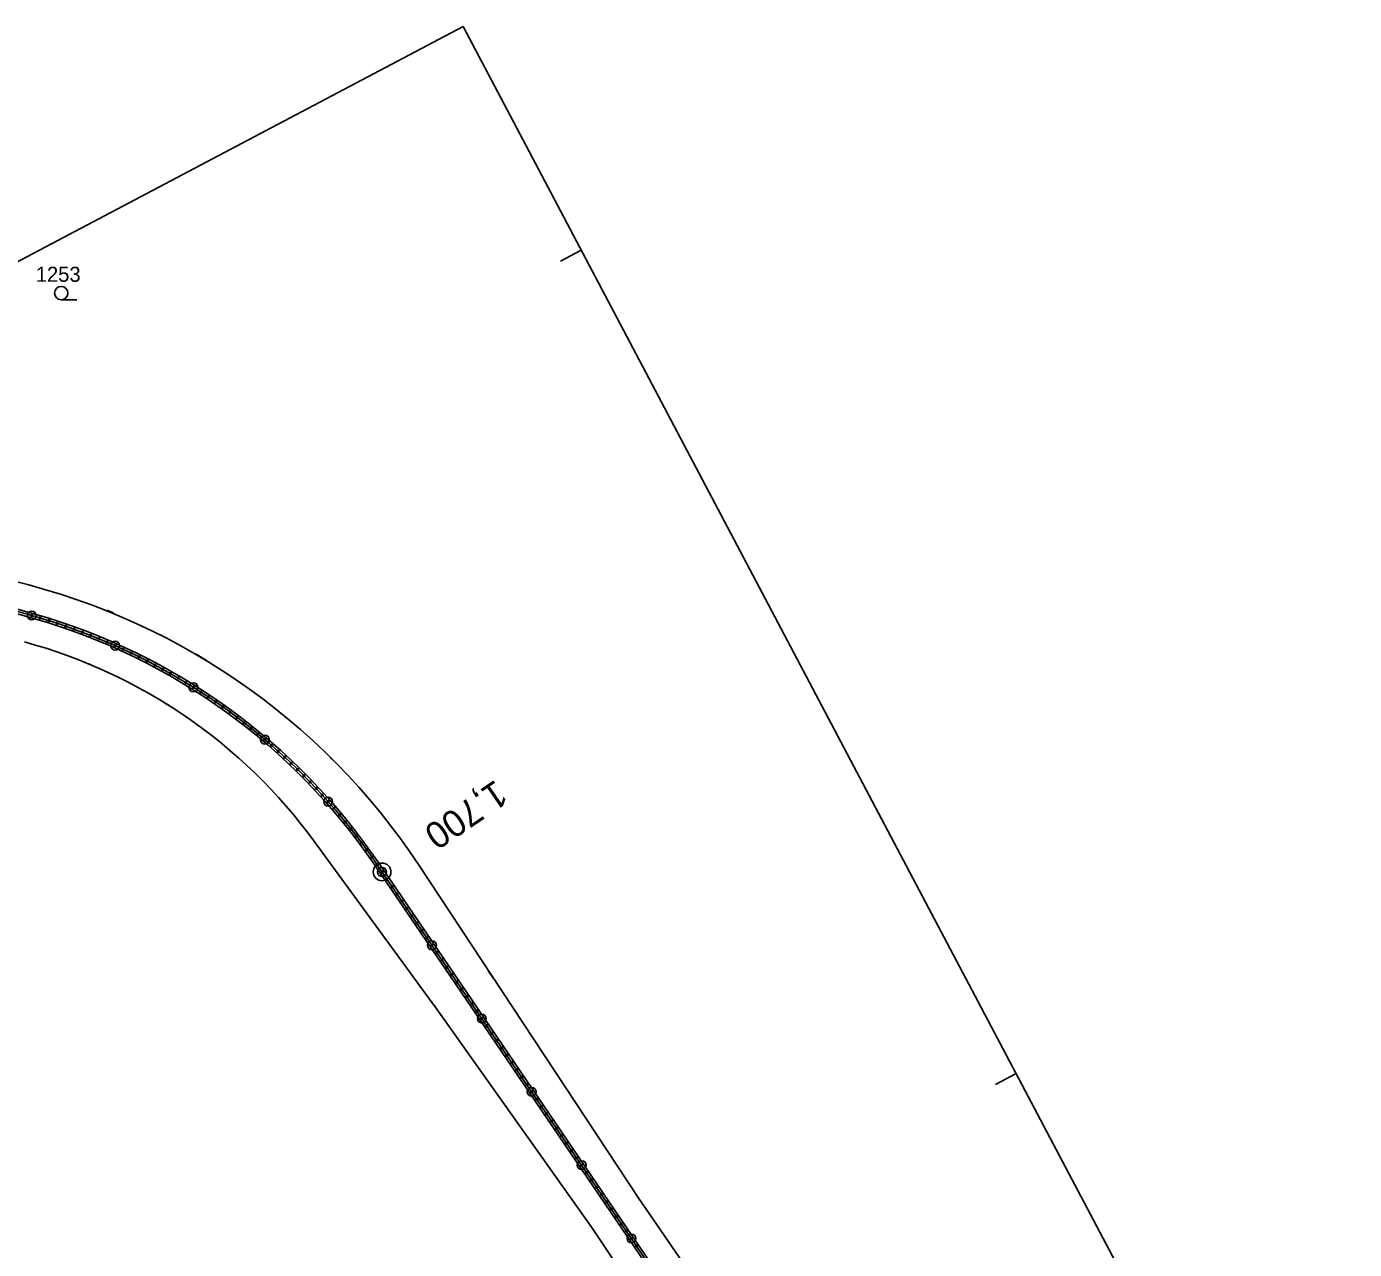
# Model space of a CAD drawing. Extents: x -548552 to -543113, y -1131925 to -1123599.
# Drawn here: x -547829.2 to -547679.4, y -1125239.2 to -1125101.2 of the extents above; entities that cross this region are included whole.
import ezdxf

# ---------------------------------------------------------------- set-up
doc = ezdxf.new("R2010")
doc.units = 0
for name, color, linetype in [('Parcelní čísla', 7, 'Continuous'), ('Poz předměty', 7, 'Continuous'), ('Profile', 7, 'Continuous'), ('STANIČENÍ', 7, 'Continuous'), ('Značky kultur', 7, 'Continuous')]:
    doc.layers.add(name, color=color, linetype=linetype)

msp = doc.modelspace()

# ---------------------------------------------------------------- linework, layer by layer
at = {"layer": 'Poz předměty'}
for p, q in [((-547828.23, -1125167.49), (-547896.71, -1125147.87)), ((-547828.37, -1125167.97), (-547896.85, -1125148.36)), ((-547782.72, -1125212.3), (-547796.76, -1125193.08)), ((-547679.86, -1125357.59), (-547789.9, -1125195.8)), ((-547679.45, -1125357.31), (-547789.49, -1125195.52)), ((-547760.22, -1125233.31), (-547784.9, -1125195.85)), ((-547782.72, -1125212.3), (-547765.35, -1125236.8)), ((-547740.66, -1125261.61), (-547760.22, -1125233.31)), ((-547765.35, -1125236.8), (-547746.25, -1125265.42))]:
    msp.add_line(p, q, dxfattribs=at)
for centre, radius, start, end in [((-547848.33, -1125237.64), 75.96, 33.3821, 78.0062), ((-547847.58, -1125235.02), 70.25, 34.2214, 74.0151), ((-547847.58, -1125235.02), 69.75, 34.2214, 74.0151), ((-547845.05, -1125228.36), 59.81, 36.1497, 74.837)]:
    msp.add_arc(centre, radius, start, end, dxfattribs=at)
at = {"layer": 'Profile'}
for p, q in [((-547831.77, -1125128.58), (-547779.94, -1125101.22)), ((-547779.94, -1125101.22), (-547735.21, -1125185.94)), ((-547766.62, -1125126.45), (-547768.95, -1125127.68)), ((-547735.21, -1125185.94), (-547680.31, -1125289.91)), ((-547717.59, -1125219.3), (-547719.93, -1125220.54))]:
    msp.add_line(p, q, dxfattribs=at)
at = {"layer": 'STANIČENÍ'}
for p, q in [((-547828.3, -1125167.73), (-547896.78, -1125148.12)), ((-547679.66, -1125357.45), (-547789.7, -1125195.66)), ((-547776.5, -1125208.59), (-547777.07, -1125207.75)), ((-547782.41, -1125212.75), (-547783.19, -1125211.6)), ((-547760.01, -1125233.61), (-547760.4, -1125233.04)), ((-547765.09, -1125237.19), (-547765.53, -1125236.53))]:
    msp.add_line(p, q, dxfattribs=at)
for centre, radius in [((-547828.57, -1125167.65), 0.5), ((-547828.57, -1125167.65), 0.1), ((-547827.61, -1125167.93), 0.1), ((-547826.65, -1125168.22), 0.1), ((-547825.7, -1125168.53), 0.1), ((-547824.75, -1125168.85), 0.1), ((-547823.81, -1125169.18), 0.1), ((-547822.87, -1125169.53), 0.1), ((-547821.94, -1125169.89), 0.1), ((-547821.01, -1125170.26), 0.1), ((-547820.09, -1125170.65), 0.1), ((-547819.17, -1125171.05), 0.5), ((-547819.17, -1125171.05), 0.1), ((-547818.26, -1125171.46), 0.1), ((-547817.36, -1125171.88), 0.1), ((-547816.46, -1125172.32), 0.1), ((-547815.57, -1125172.77), 0.1), ((-547814.68, -1125173.24), 0.1), ((-547813.8, -1125173.71), 0.1), ((-547812.93, -1125174.2), 0.1), ((-547812.06, -1125174.7), 0.1), ((-547811.2, -1125175.22), 0.1), ((-547810.35, -1125175.74), 0.5), ((-547810.35, -1125175.74), 0.1), ((-547809.51, -1125176.28), 0.1), ((-547808.68, -1125176.83), 0.1), ((-547807.85, -1125177.39), 0.1), ((-547807.03, -1125177.96), 0.1), ((-547806.22, -1125178.55), 0.1), ((-547805.42, -1125179.15), 0.1), ((-547804.62, -1125179.75), 0.1), ((-547803.84, -1125180.37), 0.1), ((-547803.06, -1125181), 0.1), ((-547802.29, -1125181.65), 0.5), ((-547802.29, -1125181.65), 0.1), ((-547801.54, -1125182.3), 0.1), ((-547800.79, -1125182.96), 0.1), ((-547800.05, -1125183.63), 0.1), ((-547799.32, -1125184.32), 0.1), ((-547798.6, -1125185.01), 0.1), ((-547797.89, -1125185.72), 0.1), ((-547797.19, -1125186.43), 0.1), ((-547796.5, -1125187.16), 0.1), ((-547795.82, -1125187.89), 0.1), ((-547795.16, -1125188.64), 0.5), ((-547795.16, -1125188.64), 0.1), ((-547794.5, -1125189.39), 0.1), ((-547793.85, -1125190.15), 0.1), ((-547793.22, -1125190.93), 0.1), ((-547792.59, -1125191.71), 0.1), ((-547791.98, -1125192.5), 0.1), ((-547791.38, -1125193.29), 0.1), ((-547790.79, -1125194.1), 0.1), ((-547790.21, -1125194.92), 0.1), ((-547789.08, -1125196.57), 1), ((-547789.64, -1125195.74), 0.1), ((-547789.08, -1125196.57), 0.5), ((-547789.08, -1125196.57), 0.1), ((-547788.52, -1125197.39), 0.1), ((-547787.95, -1125198.22), 0.1), ((-547787.39, -1125199.05), 0.1), ((-547786.83, -1125199.88), 0.1), ((-547786.27, -1125200.7), 0.1), ((-547785.7, -1125201.53), 0.1), ((-547785.14, -1125202.36), 0.1), ((-547784.58, -1125203.18), 0.1), ((-547784.02, -1125204.01), 0.1), ((-547783.45, -1125204.84), 0.5), ((-547783.45, -1125204.84), 0.1), ((-547782.89, -1125205.66), 0.1), ((-547782.33, -1125206.49), 0.1), ((-547781.77, -1125207.32), 0.1), ((-547781.2, -1125208.14), 0.1), ((-547780.64, -1125208.97), 0.1), ((-547780.08, -1125209.8), 0.1), ((-547779.52, -1125210.62), 0.1), ((-547778.95, -1125211.45), 0.1), ((-547778.39, -1125212.28), 0.1), ((-547777.83, -1125213.11), 0.5), ((-547777.83, -1125213.11), 0.1), ((-547777.27, -1125213.93), 0.1), ((-547776.71, -1125214.76), 0.1), ((-547776.14, -1125215.59), 0.1), ((-547775.58, -1125216.41), 0.1), ((-547775.02, -1125217.24), 0.1), ((-547774.46, -1125218.07), 0.1), ((-547773.89, -1125218.89), 0.1), ((-547773.33, -1125219.72), 0.1), ((-547772.77, -1125220.55), 0.1), ((-547772.21, -1125221.37), 0.5), ((-547772.21, -1125221.37), 0.1), ((-547771.64, -1125222.2), 0.1), ((-547771.08, -1125223.03), 0.1), ((-547770.52, -1125223.85), 0.1), ((-547769.96, -1125224.68), 0.1), ((-547769.39, -1125225.51), 0.1), ((-547768.83, -1125226.34), 0.1), ((-547768.27, -1125227.16), 0.1), ((-547767.71, -1125227.99), 0.1), ((-547767.14, -1125228.82), 0.1), ((-547766.58, -1125229.64), 0.5), ((-547766.58, -1125229.64), 0.1), ((-547766.02, -1125230.47), 0.1), ((-547765.46, -1125231.3), 0.1), ((-547764.89, -1125232.12), 0.1), ((-547764.33, -1125232.95), 0.1), ((-547763.77, -1125233.78), 0.1), ((-547763.21, -1125234.6), 0.1), ((-547762.65, -1125235.43), 0.1), ((-547762.08, -1125236.26), 0.1), ((-547761.52, -1125237.08), 0.1), ((-547760.96, -1125237.91), 0.5), ((-547760.96, -1125237.91), 0.1), ((-547760.4, -1125238.74), 0.1)]:
    msp.add_circle(centre, radius, dxfattribs=at)
for radius, start, end in [(73.31, 67.359, 67.9903), (70, 34.2214, 74.0151), (73.35, 58.1569, 59.2247), (66.93, 67.2987, 68.0996), (66.8, 58.2176, 59.2752), (73.57, 44.0041, 44.9993)]:
    msp.add_arc((-547847.58, -1125235.02), radius, start, end, dxfattribs=at)
at = {"layer": 'Značky kultur'}
msp.add_line((-547825.25, -1125132.03), (-547823.5, -1125132.03), dxfattribs=at)
msp.add_circle((-547825.25, -1125131.28), 0.75, dxfattribs=at)

# ---------------------------------------------------------------- texts
at = {"layer": 'Parcelní čísla'}
msp.add_text('1253', height=1.7, dxfattribs=at).set_placement((-547828.12, -1125130.01))
at = {"layer": 'STANIČENÍ'}
msp.add_text('1,700', height=3, rotation=214.2214, dxfattribs=at).set_placement((-547776.27, -1125186.08))

doc.saveas('drawing.dxf')
